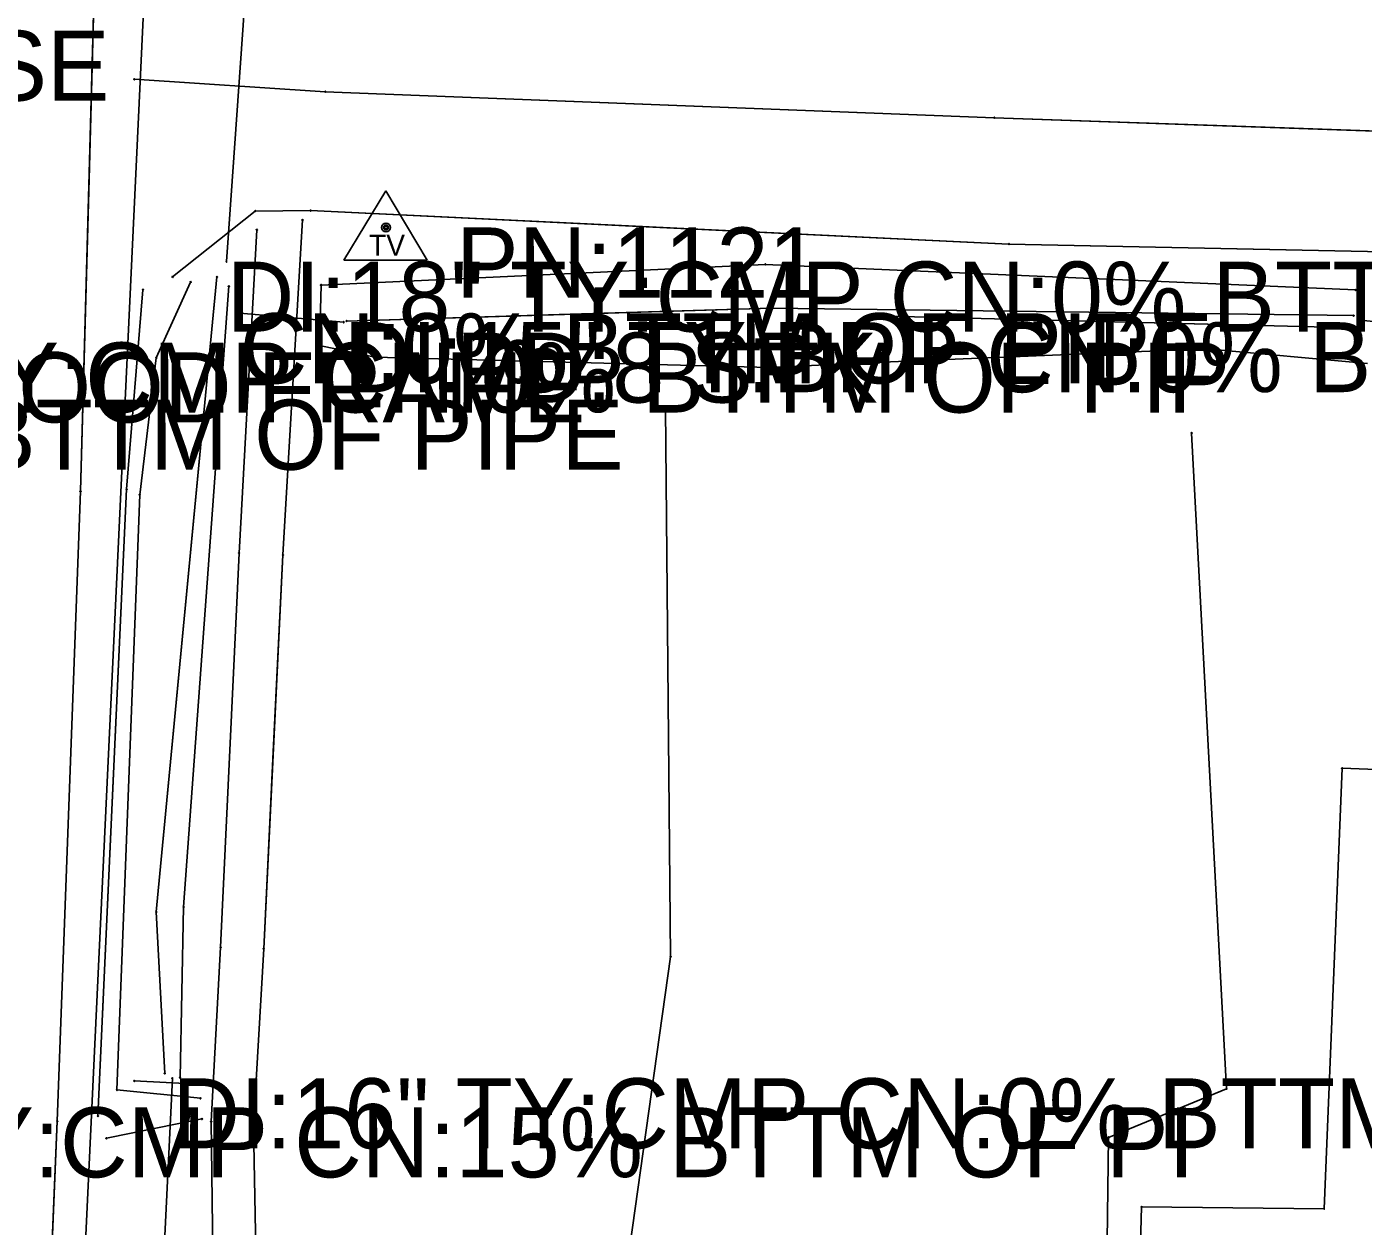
# Model space of a CAD drawing. Extents: x -99999 to 591807, y -99999 to 347168.
# Drawn here: x 591265.8 to 591361.2, y 320815.7 to 320901.3 of the extents above; entities that cross this region are included whole.
import ezdxf

# ---------------------------------------------------------------- set-up
doc = ezdxf.new("R2010")
doc.units = 0
for name, color, linetype in [('S_BREAKLINE', 7, 'Continuous'), ('S_BUILDING', 7, 'Continuous'), ('S_DITCHLINE', 7, 'Continuous'), ('S_DRG_PT_SYM', 7, 'Continuous'), ('S_DRIVEWAY', 7, 'Continuous'), ('S_EDGE_PAVEMENT', 7, 'Continuous'), ('S_GRD_PT_SYM', 7, 'Continuous'), ('S_HEADWALL', 7, 'Continuous'), ('S_MSC_PT_SYM', 7, 'Continuous'), ('S_PAVEMENT_CROWN', 7, 'Continuous'), ('S_RDW_PT_SYM', 7, 'Continuous'), ('S_SECONDARY_CTL', 7, 'Continuous'), ('S_SECONDARY_CTL_ANNOT', 7, 'Continuous'), ('S_SHOULDER', 7, 'Continuous'), ('S_SIDE_DRAIN', 7, 'Continuous'), ('S_SIDE_DRAIN_ANNOT', 7, 'Continuous'), ('S_SIDEWALK', 7, 'Continuous'), ('S_STR_PT_SYM', 7, 'Continuous'), ('S_SURVEY_TEXT_ANNOT', 7, 'Continuous'), ('S_WATER_UTILITIES', 7, 'Continuous')]:
    doc.layers.add(name, color=color, linetype=linetype)

msp = doc.modelspace()

# ---------------------------------------------------------------- linework, layer by layer
at = {"layer": 'S_BREAKLINE'}
for points in [[(591360.642, 320882.495), (591318.502, 320884.319), (591286.806, 320882.84)], [(591277.485, 320883.062), (591275.032, 320877.648), (591273.851, 320867.883), (591272.227, 320825.399), (591278.186, 320824.795)], [(591361.495, 320877.238), (591350.008, 320878.286), (591326.284, 320877.323), (591318.808, 320876.953), (591290.626, 320877.705), (591286.676, 320878.524), (591286.806, 320882.84)], [(591311.376, 320874.042), (591311.748, 320834.905), (591304.927, 320786.43), (591302.834, 320773.848)], [(591348.942, 320872.286), (591351.427, 320825.484), (591343.005, 320821.997), (591342.497, 320783.289), (591319.45, 320785.697), (591318.243, 320773.636)]]:
    msp.add_lwpolyline(points, dxfattribs=at)
at = {"layer": 'S_BUILDING'}
for p, q in [((591358.409, 320816.912), (591359.685, 320848.353)), ((591359.685, 320848.353), (591386.299, 320847.394)), ((591344.776, 320794.918), (591345.373, 320817.041)), ((591345.373, 320817.041), (591358.409, 320816.912))]:
    msp.add_line(p, q, dxfattribs=at)
at = {"layer": 'S_DITCHLINE'}
for points in [[(591279.362, 320883.425), (591275.037, 320838.103), (591275.64, 320826.577)], [(591279.362, 320883.425), (591277.199, 320860.764), (591275.037, 320838.103), (591275.64, 320826.577)], [(591280.214, 320882.756), (591276.985, 320838.457), (591276.732, 320826.273)], [(591280.214, 320882.756), (591278.599, 320860.606), (591276.985, 320838.457), (591276.732, 320826.273)], [(591360.495, 320880.665), (591318.96, 320881.206), (591288.62, 320880.271)], [(591360.495, 320880.665), (591339.727, 320880.935), (591318.96, 320881.206), (591303.79, 320880.739), (591288.62, 320880.271)], [(591360.552, 320879.8), (591326.295, 320880.66)], [(591360.552, 320879.8), (591343.423, 320880.23), (591326.295, 320880.66)]]:
    msp.add_lwpolyline(points, dxfattribs=at)
at = {"layer": 'S_DRG_PT_SYM'}
for points in [[(591280.056, 320884.524), (591280.056, 320884.574), (591280.056, 320884.524), (591280.006, 320884.524), (591280.056, 320884.524), (591280.056, 320884.474), (591280.056, 320884.524), (591280.106, 320884.524)], [(591280.989, 320880.833), (591280.989, 320880.883), (591280.989, 320880.833), (591280.939, 320880.833), (591280.989, 320880.833), (591280.989, 320880.783), (591280.989, 320880.833), (591281.039, 320880.833)], [(591360.976, 320880.337), (591360.976, 320880.386), (591360.976, 320880.337), (591360.925, 320880.337), (591360.976, 320880.337), (591360.976, 320880.286), (591360.976, 320880.337), (591361.025, 320880.337)], [(591288.422, 320880.198), (591288.422, 320880.247), (591288.422, 320880.198), (591288.372, 320880.198), (591288.422, 320880.198), (591288.422, 320880.148), (591288.422, 320880.198), (591288.472, 320880.198)], [(591276.183, 320826.223), (591276.183, 320826.273), (591276.183, 320826.223), (591276.133, 320826.223), (591276.183, 320826.223), (591276.183, 320826.173), (591276.183, 320826.223), (591276.233, 320826.223)]]:
    msp.add_lwpolyline(points, dxfattribs=at)
at = {"layer": 'S_DRIVEWAY'}
msp.add_lwpolyline([(591271.48, 320821.939), (591278.3, 320823.319)], dxfattribs=at)
msp.add_lwpolyline([(591271.48, 320821.939), (591278.3, 320823.319)], dxfattribs=at)
at = {"layer": 'S_EDGE_PAVEMENT'}
for points in [[(591276.464, 321095.169), (591275.056, 321053.597), (591273.291, 321005.346), (591272, 320957.38), (591270.852, 320912.706), (591269.626, 320868.123), (591267.967, 320823.162), (591266.366, 320784.972), (591264.567, 320741.355), (591263.052, 320704.522), (591261.343, 320660.719), (591259.642, 320623.868), (591258.44, 320586.063), (591256.824, 320543.024), (591255.332, 320500.726), (591253.745, 320460.208), (591252.238, 320423.96)], [(591270.852, 320912.706), (591270.239, 320890.414), (591269.626, 320868.123), (591268.797, 320845.643), (591267.967, 320823.162), (591267.166, 320804.067), (591266.366, 320784.972), (591265.466, 320763.163), (591264.567, 320741.355), (591263.809, 320722.939), (591263.052, 320704.522), (591262.197, 320682.621), (591261.343, 320660.719), (591260.492, 320642.293), (591259.642, 320623.868), (591259.041, 320604.965), (591258.44, 320586.063)], [(591276.196, 320883.425), (591282.099, 320888.125), (591286.056, 320888.161), (591335.899, 320885.769), (591377.781, 320884.915), (591418.934, 320882.132), (591459.848, 320880.587), (591464.913, 320873.575), (591473.579, 320855.582)], [(591276.196, 320883.425), (591282.099, 320888.125), (591286.056, 320888.161), (591310.978, 320886.965), (591335.899, 320885.769), (591356.84, 320885.342), (591377.781, 320884.915), (591398.357, 320883.523), (591418.934, 320882.132), (591439.391, 320881.359), (591459.848, 320880.587), (591464.913, 320873.575), (591473.579, 320855.582)]]:
    msp.add_lwpolyline(points, dxfattribs=at)
at = {"layer": 'S_GRD_PT_SYM'}
for points in [[(591318.502, 320884.319), (591318.505, 320884.269), (591318.502, 320884.319), (591318.552, 320884.321), (591318.502, 320884.319), (591318.5, 320884.369), (591318.502, 320884.319), (591318.453, 320884.316)], [(591279.362, 320883.425), (591279.412, 320883.42), (591279.362, 320883.425), (591279.367, 320883.474), (591279.362, 320883.425), (591279.312, 320883.429), (591279.362, 320883.425), (591279.357, 320883.375)], [(591277.485, 320883.062), (591277.53, 320883.041), (591277.485, 320883.062), (591277.505, 320883.107), (591277.485, 320883.062), (591277.439, 320883.082), (591277.485, 320883.062), (591277.464, 320883.016)], [(591280.214, 320882.756), (591280.264, 320882.752), (591280.214, 320882.756), (591280.218, 320882.806), (591280.214, 320882.756), (591280.164, 320882.759), (591280.214, 320882.756), (591280.21, 320882.706)], [(591286.806, 320882.84), (591286.756, 320882.841), (591286.806, 320882.84), (591286.805, 320882.79), (591286.806, 320882.84), (591286.856, 320882.838), (591286.806, 320882.84), (591286.808, 320882.89)], [(591286.806, 320882.84), (591286.809, 320882.79), (591286.806, 320882.84), (591286.856, 320882.842), (591286.806, 320882.84), (591286.804, 320882.89), (591286.806, 320882.84), (591286.756, 320882.837)], [(591360.642, 320882.495), (591360.64, 320882.445), (591360.642, 320882.495), (591360.692, 320882.493), (591360.642, 320882.495), (591360.645, 320882.545), (591360.642, 320882.495), (591360.593, 320882.497)], [(591318.96, 320881.206), (591318.961, 320881.156), (591318.96, 320881.206), (591319.01, 320881.207), (591318.96, 320881.206), (591318.958, 320881.256), (591318.96, 320881.206), (591318.91, 320881.204)], [(591288.62, 320880.271), (591288.622, 320880.222), (591288.62, 320880.271), (591288.67, 320880.273), (591288.62, 320880.271), (591288.619, 320880.321), (591288.62, 320880.271), (591288.57, 320880.27)], [(591326.295, 320880.66), (591326.294, 320880.61), (591326.295, 320880.66), (591326.345, 320880.658), (591326.295, 320880.66), (591326.296, 320880.71), (591326.295, 320880.66), (591326.245, 320880.661)], [(591360.495, 320880.665), (591360.494, 320880.615), (591360.495, 320880.665), (591360.544, 320880.664), (591360.495, 320880.665), (591360.495, 320880.715), (591360.495, 320880.665), (591360.445, 320880.665)], [(591360.552, 320879.8), (591360.55, 320879.75), (591360.552, 320879.8), (591360.601, 320879.798), (591360.552, 320879.8), (591360.553, 320879.849), (591360.552, 320879.8), (591360.502, 320879.801)], [(591286.676, 320878.524), (591286.626, 320878.526), (591286.676, 320878.524), (591286.675, 320878.474), (591286.676, 320878.524), (591286.726, 320878.523), (591286.676, 320878.524), (591286.678, 320878.574)], [(591275.032, 320877.648), (591275.081, 320877.642), (591275.032, 320877.648), (591275.037, 320877.698), (591275.032, 320877.648), (591274.982, 320877.654), (591275.032, 320877.648), (591275.026, 320877.599)], [(591290.626, 320877.705), (591290.615, 320877.656), (591290.626, 320877.705), (591290.675, 320877.695), (591290.626, 320877.705), (591290.636, 320877.754), (591290.626, 320877.705), (591290.577, 320877.715)], [(591350.008, 320878.286), (591350.01, 320878.236), (591350.008, 320878.286), (591350.058, 320878.288), (591350.008, 320878.286), (591350.006, 320878.336), (591350.008, 320878.286), (591349.958, 320878.284)], [(591318.808, 320876.953), (591318.806, 320876.903), (591318.808, 320876.953), (591318.858, 320876.952), (591318.808, 320876.953), (591318.809, 320877.003), (591318.808, 320876.953), (591318.758, 320876.955)], [(591326.284, 320877.323), (591326.287, 320877.273), (591326.284, 320877.323), (591326.334, 320877.326), (591326.284, 320877.323), (591326.282, 320877.373), (591326.284, 320877.323), (591326.234, 320877.321)], [(591311.376, 320874.042), (591311.426, 320874.043), (591311.376, 320874.042), (591311.376, 320874.092), (591311.376, 320874.042), (591311.326, 320874.042), (591311.376, 320874.042), (591311.376, 320873.992)], [(591348.942, 320872.286), (591348.992, 320872.289), (591348.942, 320872.286), (591348.939, 320872.336), (591348.942, 320872.286), (591348.892, 320872.283), (591348.942, 320872.286), (591348.944, 320872.236)], [(591273.851, 320867.883), (591273.901, 320867.881), (591273.851, 320867.883), (591273.853, 320867.933), (591273.851, 320867.883), (591273.801, 320867.885), (591273.851, 320867.883), (591273.849, 320867.833)], [(591276.985, 320838.457), (591277.035, 320838.456), (591276.985, 320838.457), (591276.986, 320838.507), (591276.985, 320838.457), (591276.935, 320838.458), (591276.985, 320838.457), (591276.984, 320838.407)], [(591275.037, 320838.103), (591275.086, 320838.105), (591275.037, 320838.103), (591275.034, 320838.153), (591275.037, 320838.103), (591274.987, 320838.1), (591275.037, 320838.103), (591275.039, 320838.053)], [(591311.748, 320834.905), (591311.798, 320834.898), (591311.748, 320834.905), (591311.755, 320834.955), (591311.748, 320834.905), (591311.699, 320834.912), (591311.748, 320834.905), (591311.741, 320834.856)], [(591275.64, 320826.577), (591275.69, 320826.579), (591275.64, 320826.577), (591275.638, 320826.627), (591275.64, 320826.577), (591275.591, 320826.574), (591275.64, 320826.577), (591275.643, 320826.527)], [(591276.732, 320826.273), (591276.782, 320826.272), (591276.732, 320826.273), (591276.733, 320826.323), (591276.732, 320826.273), (591276.682, 320826.274), (591276.732, 320826.273), (591276.731, 320826.223)], [(591272.227, 320825.399), (591272.232, 320825.448), (591272.227, 320825.399), (591272.178, 320825.404), (591272.227, 320825.399), (591272.222, 320825.349), (591272.227, 320825.399), (591272.277, 320825.394)], [(591351.427, 320825.484), (591351.446, 320825.438), (591351.427, 320825.484), (591351.473, 320825.503), (591351.427, 320825.484), (591351.408, 320825.53), (591351.427, 320825.484), (591351.381, 320825.465)], [(591278.186, 320824.795), (591278.191, 320824.844), (591278.186, 320824.795), (591278.136, 320824.8), (591278.186, 320824.795), (591278.181, 320824.745), (591278.186, 320824.795), (591278.235, 320824.79)], [(591343.005, 320821.997), (591343.055, 320821.996), (591343.005, 320821.997), (591343.006, 320822.046), (591343.005, 320821.997), (591342.955, 320821.997), (591343.005, 320821.997), (591343.005, 320821.947)]]:
    msp.add_lwpolyline(points, close=True, dxfattribs=at)
at = {"layer": 'S_HEADWALL'}
msp.add_lwpolyline([(591278.49, 320825.792), (591273.469, 320826.035)], dxfattribs=at)
msp.add_lwpolyline([(591278.49, 320825.792), (591273.469, 320826.035)], dxfattribs=at)
at = {"layer": 'S_MSC_PT_SYM'}
for points in [[(591285.474, 320887.491), (591285.524, 320887.488), (591285.474, 320887.491), (591285.477, 320887.541), (591285.474, 320887.491), (591285.424, 320887.494), (591285.474, 320887.491), (591285.471, 320887.441)], [(591282.215, 320886.788), (591282.265, 320886.785), (591282.215, 320886.788), (591282.218, 320886.838), (591282.215, 320886.788), (591282.165, 320886.791), (591282.215, 320886.788), (591282.212, 320886.738)], [(591280.949, 320863.72), (591280.999, 320863.718), (591280.949, 320863.72), (591280.951, 320863.77), (591280.949, 320863.72), (591280.899, 320863.723), (591280.949, 320863.72), (591280.947, 320863.67)], [(591284.077, 320863.578), (591284.127, 320863.576), (591284.077, 320863.578), (591284.08, 320863.628), (591284.077, 320863.578), (591284.027, 320863.581), (591284.077, 320863.578), (591284.075, 320863.528)], [(591279.629, 320835.581), (591279.679, 320835.579), (591279.629, 320835.581), (591279.632, 320835.631), (591279.629, 320835.581), (591279.579, 320835.584), (591279.629, 320835.581), (591279.626, 320835.531)], [(591282.702, 320835.471), (591282.752, 320835.469), (591282.702, 320835.471), (591282.705, 320835.521), (591282.702, 320835.471), (591282.652, 320835.474), (591282.702, 320835.471), (591282.699, 320835.421)], [(591273.469, 320826.035), (591273.467, 320825.985), (591273.469, 320826.035), (591273.519, 320826.032), (591273.469, 320826.035), (591273.472, 320826.085), (591273.469, 320826.035), (591273.419, 320826.037)], [(591278.49, 320825.792), (591278.487, 320825.742), (591278.49, 320825.792), (591278.54, 320825.789), (591278.49, 320825.792), (591278.492, 320825.842), (591278.49, 320825.792), (591278.44, 320825.794)], [(591278.953, 320823.139), (591279.003, 320823.14), (591278.953, 320823.139), (591278.952, 320823.189), (591278.953, 320823.139), (591278.903, 320823.139), (591278.953, 320823.139), (591278.953, 320823.09)], [(591281.975, 320822.837), (591282.025, 320822.837), (591281.975, 320822.837), (591281.974, 320822.886), (591281.975, 320822.837), (591281.925, 320822.836), (591281.975, 320822.837), (591281.976, 320822.787)]]:
    msp.add_lwpolyline(points, close=True, dxfattribs=at)
at = {"layer": 'S_PAVEMENT_CROWN'}
for points in [[(591273.47, 320897.534), (591287.099, 320896.647), (591334.851, 320894.786), (591377.656, 320893.291), (591416.768, 320890.774), (591460.018, 320889.148), (591498.261, 320886.474), (591538.694, 320883.646), (591580.868, 320882.065)], [(591273.47, 320897.534), (591287.099, 320896.647), (591310.975, 320895.717), (591334.851, 320894.786), (591356.253, 320894.039), (591377.656, 320893.291), (591397.212, 320892.033), (591416.768, 320890.774), (591438.393, 320889.961), (591460.018, 320889.148), (591479.14, 320887.811), (591498.261, 320886.474), (591518.478, 320885.06), (591538.694, 320883.646), (591559.781, 320882.855), (591580.868, 320882.065)]]:
    msp.add_lwpolyline(points, dxfattribs=at)
at = {"layer": 'S_RDW_PT_SYM'}
for points in [[(591273.47, 320897.534), (591273.474, 320897.584), (591273.47, 320897.534), (591273.421, 320897.537), (591273.47, 320897.534), (591273.467, 320897.484), (591273.47, 320897.534), (591273.52, 320897.53)], [(591287.099, 320896.647), (591287.101, 320896.697), (591287.099, 320896.647), (591287.049, 320896.649), (591287.099, 320896.647), (591287.097, 320896.597), (591287.099, 320896.647), (591287.149, 320896.645)], [(591334.851, 320894.786), (591334.852, 320894.836), (591334.851, 320894.786), (591334.801, 320894.788), (591334.851, 320894.786), (591334.849, 320894.737), (591334.851, 320894.786), (591334.901, 320894.785)], [(591282.099, 320888.125), (591282.099, 320888.175), (591282.099, 320888.125), (591282.049, 320888.125), (591282.099, 320888.125), (591282.099, 320888.075), (591282.099, 320888.125), (591282.149, 320888.126)], [(591286.056, 320888.161), (591286.059, 320888.211), (591286.056, 320888.161), (591286.006, 320888.163), (591286.056, 320888.161), (591286.054, 320888.111), (591286.056, 320888.161), (591286.106, 320888.159)], [(591335.899, 320885.769), (591335.9, 320885.819), (591335.899, 320885.769), (591335.849, 320885.77), (591335.899, 320885.769), (591335.898, 320885.719), (591335.899, 320885.769), (591335.949, 320885.768)], [(591276.196, 320883.425), (591276.164, 320883.464), (591276.196, 320883.425), (591276.156, 320883.394), (591276.196, 320883.425), (591276.227, 320883.386), (591276.196, 320883.425), (591276.235, 320883.456)], [(591274.079, 320882.51), (591274.129, 320882.506), (591274.079, 320882.51), (591274.083, 320882.56), (591274.079, 320882.51), (591274.03, 320882.514), (591274.079, 320882.51), (591274.075, 320882.46)], [(591269.626, 320868.123), (591269.676, 320868.121), (591269.626, 320868.123), (591269.628, 320868.173), (591269.626, 320868.123), (591269.576, 320868.125), (591269.626, 320868.123), (591269.624, 320868.073)], [(591272.919, 320868.268), (591272.969, 320868.265), (591272.919, 320868.268), (591272.922, 320868.318), (591272.919, 320868.268), (591272.869, 320868.27), (591272.919, 320868.268), (591272.917, 320868.218)], [(591267.967, 320823.162), (591268.017, 320823.16), (591267.967, 320823.162), (591267.969, 320823.212), (591267.967, 320823.162), (591267.917, 320823.165), (591267.967, 320823.162), (591267.965, 320823.113)], [(591270.87, 320823.525), (591270.92, 320823.522), (591270.87, 320823.525), (591270.872, 320823.575), (591270.87, 320823.525), (591270.82, 320823.527), (591270.87, 320823.525), (591270.868, 320823.475)], [(591278.3, 320823.319), (591278.29, 320823.368), (591278.3, 320823.319), (591278.251, 320823.309), (591278.3, 320823.319), (591278.31, 320823.27), (591278.3, 320823.319), (591278.349, 320823.329)], [(591271.48, 320821.939), (591271.47, 320821.989), (591271.48, 320821.939), (591271.431, 320821.93), (591271.48, 320821.939), (591271.49, 320821.89), (591271.48, 320821.939), (591271.529, 320821.949)]]:
    msp.add_lwpolyline(points, close=True, dxfattribs=at)
at = {"layer": 'S_SECONDARY_CTL'}
for p, q in [((591291.433, 320889.566), (591288.423, 320884.612)), ((591291.433, 320889.566), (591294.38, 320884.612)), ((591288.423, 320884.612), (591294.38, 320884.612))]:
    msp.add_line(p, q, dxfattribs=at)
for radius in [0.311, 0.183, 0.103]:
    msp.add_circle((591291.433, 320886.956), radius, dxfattribs=at)
at = {"layer": 'S_SHOULDER'}
for points in [[(591274.079, 320882.51), (591272.919, 320868.268), (591270.87, 320823.525)], [(591274.079, 320882.51), (591272.919, 320868.268), (591271.895, 320845.896), (591270.87, 320823.525)]]:
    msp.add_lwpolyline(points, dxfattribs=at)
at = {"layer": 'S_SIDE_DRAIN'}
for p, q in [((591280.056, 320884.524), (591281.825, 320909.839)), ((591288.422, 320880.198), (591280.989, 320880.833)), ((591381.254, 320878.371), (591360.976, 320880.337)), ((591276.183, 320826.223), (591274.993, 320801.341))]:
    msp.add_line(p, q, dxfattribs=at)
at = {"layer": 'S_SIDEWALK'}
for points in [[(591285.474, 320887.491), (591284.077, 320863.578), (591282.702, 320835.471), (591281.975, 320822.837), (591282.437, 320798.787), (591281.77, 320774.693), (591300.391, 320773.507), (591318.704, 320772.615)], [(591285.474, 320887.491), (591284.077, 320863.578), (591283.39, 320849.525), (591282.702, 320835.471), (591281.975, 320822.837), (591282.437, 320798.787), (591281.77, 320774.693), (591300.391, 320773.507), (591318.704, 320772.615)], [(591282.215, 320886.788), (591280.949, 320863.72), (591279.629, 320835.581), (591278.953, 320823.139), (591279.257, 320798.673), (591278.238, 320770.333), (591275.823, 320751.245), (591275.039, 320735.163)], [(591282.215, 320886.788), (591280.949, 320863.72), (591280.289, 320849.651), (591279.629, 320835.581), (591278.953, 320823.139), (591279.257, 320798.673), (591278.747, 320784.503), (591278.238, 320770.333), (591275.823, 320751.245), (591275.039, 320735.163)]]:
    msp.add_lwpolyline(points, dxfattribs=at)
at = {"layer": 'S_STR_PT_SYM'}
for points in [[(591359.685, 320848.353), (591359.685, 320848.403), (591359.685, 320848.353), (591359.635, 320848.353), (591359.685, 320848.353), (591359.685, 320848.303), (591359.685, 320848.353), (591359.735, 320848.353)], [(591345.373, 320817.041), (591345.373, 320817.091), (591345.373, 320817.041), (591345.323, 320817.041), (591345.373, 320817.041), (591345.373, 320816.991), (591345.373, 320817.041), (591345.423, 320817.041)], [(591358.409, 320816.912), (591358.409, 320816.962), (591358.409, 320816.912), (591358.359, 320816.912), (591358.409, 320816.912), (591358.409, 320816.862), (591358.409, 320816.912), (591358.459, 320816.912)]]:
    msp.add_lwpolyline(points, dxfattribs=at)
at = {"layer": 'S_WATER_UTILITIES'}
msp.add_line((591275.027, 320921.464), (591267.261, 320756.584), dxfattribs=at)

# ---------------------------------------------------------------- texts
at = {"layer": 'S_SECONDARY_CTL'}
msp.add_text('TV', height=1.5, rotation=360, dxfattribs=at).set_placement((591290.228, 320884.945))
at = {"layer": 'S_SECONDARY_CTL_ANNOT'}
for s, p in [('PN:1121', (591296.433, 320881.956)), ('PD:8 SPK', (591296.433, 320874.456))]:
    msp.add_text(s, height=5, dxfattribs=at).set_placement(p)
at = {"layer": 'S_SIDE_DRAIN_ANNOT'}
for s, p in [('DI:18" TY:CMP CN:0% BTTM OF PIP', (591280.056, 320879.524)), ('CN:0% BTTM OF PIPE', (591280.989, 320875.833)), ('DI:15" TY:BPP CN:0% BTTM OF PIP', (591288.422, 320875.198)), ('DI:16" TY:CMP CN:0% BTTM OF PIP', (591239.349, 320873.746)), ('CN:0% BTTM OF PIPE', (591238.928, 320869.665)), ('DI:16" TY:CMP CN:0% BTTM OF PIP', (591276.183, 320821.223)), ('DI:18" TY:CMP CN:15% BTTM OF PI', (591237.549, 320819.153))]:
    msp.add_text(s, height=5, dxfattribs=at).set_placement(p)
at = {"layer": 'S_SURVEY_TEXT_ANNOT'}
for s, p in [('ROCK AND CONC WELLHOUSE', (591171.017, 320896.004)), ('ONE STORY WOOD FRAME', (591217.635, 320873.045))]:
    msp.add_text(s, height=5, dxfattribs=at).set_placement(p)

doc.saveas('drawing.dxf')
